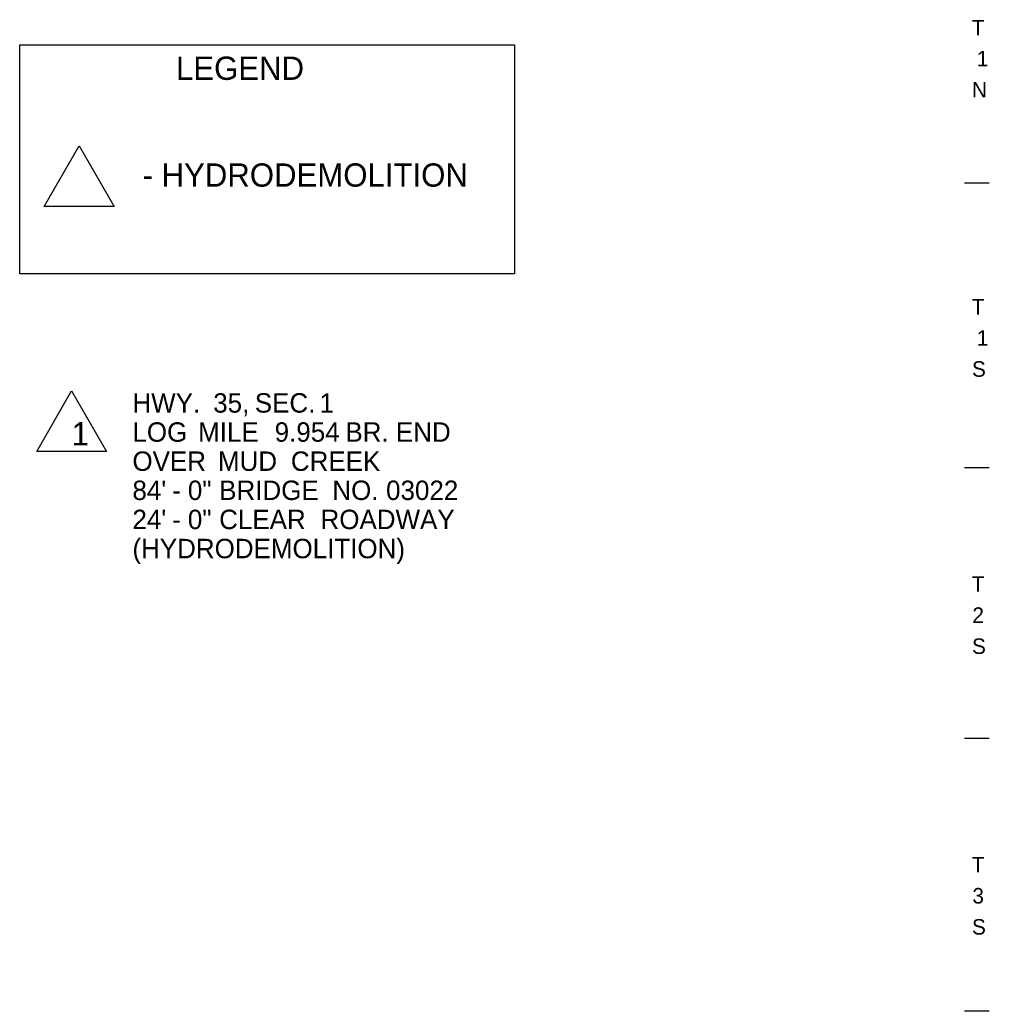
# Model space of a CAD drawing. Extents: x -42408 to 34530, y -43140 to 20491.
# Drawn here: x -17138 to -13393, y -1942 to 1888 of the extents above; entities that cross this region are included whole.
import ezdxf

# ---------------------------------------------------------------- set-up
doc = ezdxf.new("R2010")
doc.units = 0
for name, color, linetype in [('2', 7, 'Continuous'), ('30', 7, 'Continuous'), ('Default', 7, 'Continuous'), ('S_MISC_BOUNDARY', 7, 'Continuous')]:
    doc.layers.add(name, color=color, linetype=linetype)

msp = doc.modelspace()

# ---------------------------------------------------------------- linework, layer by layer
at = {"layer": '30'}
for points in [[(-17138.1, 1791.9), (-15227.5, 1791.9), (-15227.5, 907.2), (-17138.1, 907.2)], [(-16908.7, 1400.6), (-16773.7, 1166.8), (-17043.7, 1166.8)], [(-16938, 454.5), (-16803, 220.6), (-17073, 220.6)]]:
    msp.add_lwpolyline(points, close=True, dxfattribs=at)
at = {"layer": 'Default'}
for p, q in [((-13393.3, 1257.6), (-13488.3, 1257.6)), ((-13392.9, 156.8), (-13487.9, 156.8)), ((-13393.3, -888.6), (-13488.3, -888.6)), ((-13393.3, -1941.5), (-13488.3, -1941.5))]:
    msp.add_line(p, q, dxfattribs=at)
at = {"layer": 'S_MISC_BOUNDARY'}
msp.add_line((-16703, 445.6), (-16703, 445.6), dxfattribs=at)

# ---------------------------------------------------------------- texts
at = {"layer": '2'}
for s, p in [('T', (-13460.4, 1827.9)), ('1', (-13440.8, 1707.9)), ('N', (-13459.5, 1587.9)), ('T', (-13460.4, 749.1)), ('1', (-13440.8, 629.1)), ('S', (-13459.3, 509.1)), ('T', (-13460.4, -321.6)), ('2', (-13457.8, -441.6)), ('S', (-13459.3, -561.6)), ('T', (-13460.4, -1405.7)), ('3', (-13457.8, -1525.7)), ('S', (-13459.3, -1645.7))]:
    msp.add_text(s, height=60, dxfattribs=at).set_placement(p)
at = {"layer": '30'}
for s, p in [('LEGEND', (-16534.7, 1656)), ('- HYDRODEMOLITION', (-16664, 1243.4)), ('1', (-16937.9, 244))]:
    msp.add_text(s, height=90, dxfattribs=at).set_placement(p)
at = {"layer": 'Default'}
for s, p in [('HWY.', (-16703, 370.6)), (' 35,', (-16418.7, 370.6)), (' SEC.', (-16258.2, 370.6)), (' 1', (-16007.6, 370.6)), ('LOG', (-16703, 258.1)), (' MILE', (-16477.1, 258.1)), (' 9.954', (-16181.3, 258.1)), (' BR.', (-15908.1, 258.1)), (' END', (-15712.9, 258.1)), ('OVER', (-16703, 145.6)), (' MUD', (-16400.6, 145.6)), (' CREEK', (-16118.7, 145.6)), ("84'", (-16703, 33.1)), (' 0"', (-16516.7, 33.1)), (' BRIDGE', (-16395.7, 33.1)), (' NO.', (-15958.4, 33.1)), (' 03022', (-15750.9, 33.1)), (' -', (-16576.9, 33.1)), ("24'", (-16703, -79.4)), (' 0"', (-16516.7, -79.4)), (' CLEAR', (-16395.7, -79.4)), (' ROADWAY', (-16004.1, -79.4)), (' -', (-16576.9, -79.4)), ('(HYDRODEMOLITION)', (-16703, -191.9))]:
    msp.add_text(s, height=75, dxfattribs=at).set_placement(p)

doc.saveas('drawing.dxf')
